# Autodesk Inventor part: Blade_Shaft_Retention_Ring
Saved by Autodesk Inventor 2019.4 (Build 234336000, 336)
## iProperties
Created: 2020-04
Part Number: Blade_Shaft_Retention_Ring
Material: Generic
Document SubType Name: Modeling
Designer: Administrator
Density: 1 g/cm^3
Appearance: Default
Title: Blade_Shaft_Retention_Ring v1
Author: Administrator
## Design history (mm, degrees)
feature "Body1"
body "Solid1"
